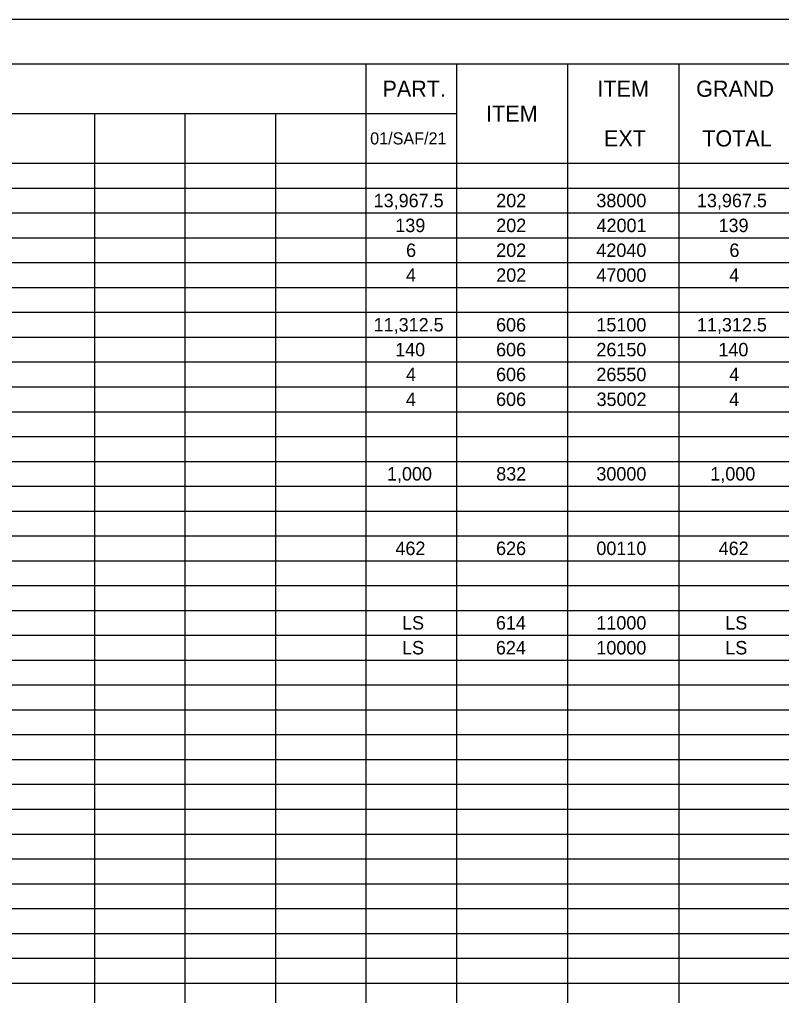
# Model space of a CAD drawing. Extents: x 0 to 34, y 0 to 22.
# Drawn here: x 8.81 to 17.41, y 11 to 22 of the extents above; entities that cross this region are included whole.
import ezdxf

# ---------------------------------------------------------------- set-up
doc = ezdxf.new("R2010")
doc.units = 0
for name, color, linetype in [('SH_Border', 7, 'Continuous'), ('SH_Cut_Line', 7, 'Continuous'), ('SH_Text', 7, 'Continuous')]:
    doc.layers.add(name, color=color, linetype=linetype)

msp = doc.modelspace()

# ---------------------------------------------------------------- linework, layer by layer
at = {"layer": 'SH_Border'}
msp.add_lwpolyline([(1.5, 21.5), (33.5, 21.5), (33.5, 0.5), (1.5, 0.5)], close=True, dxfattribs=at)
at = {"layer": 'SH_Cut_Line'}
msp.add_lwpolyline([(0, 0), (34, 0), (34, 22), (0, 22)], close=True, dxfattribs=at)
at = {"layer": 'SH_Text'}
for p, q in [((1.5, 21.5), (32, 21.5)), ((12.72, 21.5), (12.72, 0.5)), ((13.74, 21.5), (13.74, 0.5)), ((14.994, 21.5), (14.994, 0.5)), ((16.248, 21.5), (16.248, 0.5)), ((1.5, 20.94), (13.74, 20.94)), ((9.66, 20.94), (9.66, 0.5)), ((10.68, 20.94), (10.68, 0.5)), ((11.7, 20.94), (11.7, 0.5)), ((1.5, 20.38), (32, 20.38)), ((1.5, 20.1), (32, 20.1)), ((1.5, 19.82), (32, 19.82)), ((1.5, 19.54), (32, 19.54)), ((1.5, 19.26), (32, 19.26)), ((1.5, 18.98), (32, 18.98)), ((1.5, 18.7), (32, 18.7)), ((1.5, 18.42), (32, 18.42)), ((1.5, 18.14), (32, 18.14)), ((1.5, 17.86), (32, 17.86)), ((1.5, 17.58), (32, 17.58)), ((1.5, 17.3), (32, 17.3)), ((1.5, 17.02), (32, 17.02)), ((1.5, 16.74), (32, 16.74)), ((1.5, 16.46), (32, 16.46)), ((1.5, 16.18), (32, 16.18)), ((1.5, 15.9), (32, 15.9)), ((1.5, 15.62), (32, 15.62)), ((1.5, 15.34), (32, 15.34)), ((1.5, 15.06), (32, 15.06)), ((1.5, 14.78), (32, 14.78)), ((1.5, 14.5), (32, 14.5)), ((1.5, 14.22), (32, 14.22)), ((1.5, 13.94), (32, 13.94)), ((1.5, 13.66), (32, 13.66)), ((1.5, 13.38), (32, 13.38)), ((1.5, 13.1), (32, 13.1)), ((1.5, 12.82), (32, 12.82)), ((1.5, 12.54), (32, 12.54)), ((1.5, 12.26), (32, 12.26)), ((1.5, 11.98), (32, 11.98)), ((1.5, 11.7), (32, 11.7)), ((1.5, 11.42), (32, 11.42)), ((1.5, 11.14), (32, 11.14))]:
    msp.add_line(p, q, dxfattribs=at)

# ---------------------------------------------------------------- texts
for s, height, p in [('PART.', 0.1818, (12.907, 21.129)), ('ITEM', 0.1818, (15.331, 21.129)), ('GRAND', 0.1818, (16.444, 21.129)), ('ITEM', 0.1818, (14.076, 20.849)), ('01/SAF/21', 0.1364, (12.768, 20.592)), ('EXT', 0.1818, (15.405, 20.569)), ('TOTAL', 0.1818, (16.513, 20.569)), ('13,967.5', 0.1515, (12.808, 19.884)), ('202', 0.1515, (14.19, 19.884)), ('38000', 0.1515, (15.319, 19.884)), ('13,967.5', 0.1515, (16.453, 19.884)), ('139', 0.1515, (13.052, 19.604)), ('202', 0.1515, (14.19, 19.604)), ('42001', 0.1515, (15.321, 19.604)), ('139', 0.1515, (16.697, 19.604)), ('6', 0.152, (13.173, 19.324)), ('202', 0.1515, (14.19, 19.324)), ('42040', 0.1515, (15.319, 19.324)), ('6', 0.152, (16.819, 19.324)), ('4', 0.152, (13.172, 19.044)), ('202', 0.1515, (14.19, 19.044)), ('47000', 0.1515, (15.319, 19.044)), ('4', 0.152, (16.817, 19.044)), ('11,312.5', 0.1515, (12.808, 18.484)), ('606', 0.1515, (14.188, 18.484)), ('15100', 0.1515, (15.319, 18.484)), ('11,312.5', 0.1515, (16.453, 18.484)), ('140', 0.1515, (13.05, 18.204)), ('606', 0.1515, (14.188, 18.204)), ('26150', 0.1515, (15.319, 18.204)), ('140', 0.1515, (16.695, 18.204)), ('4', 0.152, (13.172, 17.924)), ('606', 0.1515, (14.188, 17.924)), ('26550', 0.1515, (15.319, 17.924)), ('4', 0.152, (16.817, 17.924)), ('4', 0.152, (13.172, 17.644)), ('606', 0.1515, (14.188, 17.644)), ('35002', 0.1515, (15.321, 17.644)), ('4', 0.152, (16.817, 17.644)), ('1,000', 0.1515, (12.958, 16.804)), ('832', 0.1515, (14.19, 16.804)), ('30000', 0.1515, (15.319, 16.804)), ('1,000', 0.1515, (16.604, 16.804)), ('462', 0.1515, (13.053, 15.964)), ('626', 0.1515, (14.188, 15.964)), ('00110', 0.1515, (15.319, 15.964)), ('462', 0.1515, (16.698, 15.964)), ('LS', 0.1515, (13.128, 15.124)), ('614', 0.1515, (14.186, 15.124)), ('11000', 0.1515, (15.319, 15.124)), ('LS', 0.1515, (16.773, 15.124)), ('LS', 0.1515, (13.128, 14.844)), ('624', 0.1515, (14.186, 14.844)), ('10000', 0.1515, (15.319, 14.844)), ('LS', 0.1515, (16.773, 14.844))]:
    msp.add_text(s, height=height, dxfattribs=at).set_placement(p)

doc.saveas('drawing.dxf')
